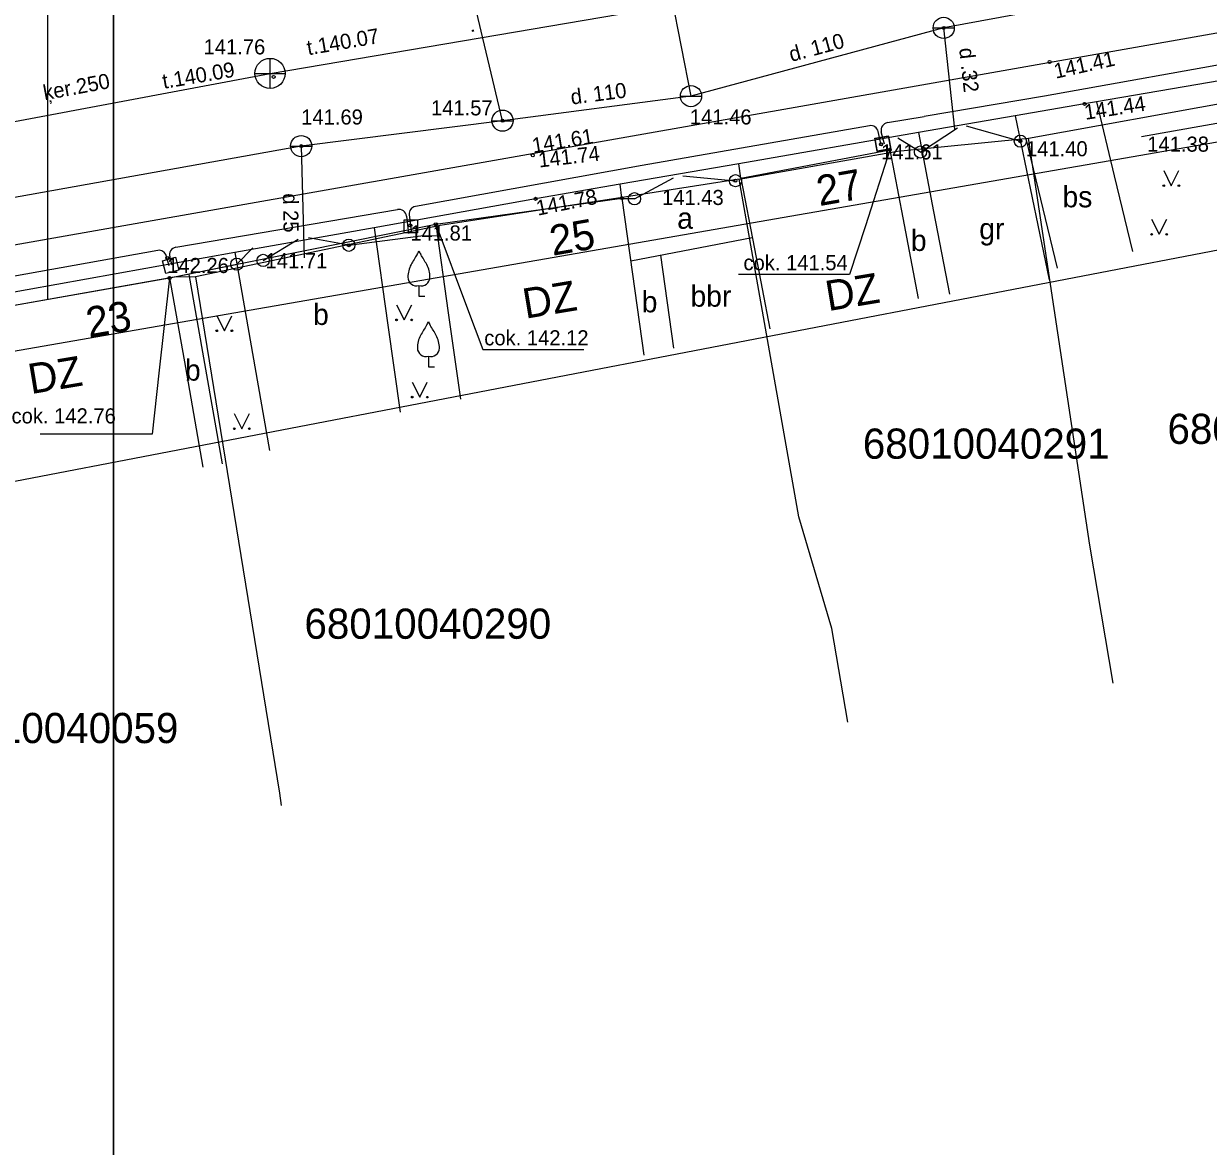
# Model space of a CAD drawing. Extents: x 728492 to 729038, y 272968 to 273171.
# Drawn here: x 728762.32 to 728801.6, y 273056.38 to 273093.59 of the extents above; entities that cross this region are included whole.
import ezdxf

# ---------------------------------------------------------------- set-up
doc = ezdxf.new("R2010")
doc.units = 0
for name, color, linetype in [('APGR_SARK_####_####_#', 7, 'Continuous'), ('BUVE_BDET_####_####_#', 7, 'Continuous'), ('BUVE_BDET_####_TKST_#', 7, 'Continuous'), ('BUVE_EKAS_####_####_#', 7, 'Continuous'), ('BUVE_EKAS_ADRS_TKST_#', 7, 'Continuous'), ('BUVE_EKAS_RAKS_TKST_#', 7, 'Continuous'), ('CELI_CAPM_####_####_#', 7, 'Continuous'), ('CELI_CMAL_####_####_#', 7, 'Continuous'), ('CELI_CSEG_####_TKST_#', 7, 'Continuous'), ('CELI_SEGL_####_####_#', 7, 'Continuous'), ('ELEK_ELEM_####_####_#', 7, 'Continuous'), ('ELEK_VADP_ZSPR_####_I', 7, 'Continuous'), ('NORB_ELEM_####_####_#', 7, 'Continuous'), ('NORB_ZOGS_BARJ_####_#', 7, 'Continuous'), ('NORB_ZOGS_ZSTP_####_#', 7, 'Continuous'), ('RAMI_PLAN_####_TKST_#', 7, 'Continuous'), ('RAMI_UZMR_####_####_#', 7, 'Continuous'), ('RELJ_AATZ_####_TKST_#', 7, 'Continuous'), ('RELJ_ELEM_####_####_#', 7, 'Continuous'), ('ROBZ_KADS_####_TKST_#', 7, 'Continuous'), ('ROBZ_UZMR_####_####_#', 7, 'Continuous'), ('SAKT_VADV_KLIN_####_#', 7, 'Continuous'), ('SKAN_ELEM_####_####_#', 7, 'Continuous'), ('SKAN_VADP_PAST_####_#', 7, 'Continuous'), ('SKAN_VADP_PAST_TKST_#', 7, 'Continuous'), ('TERT_ELEM_####_####_#', 7, 'Continuous'), ('TERT_KRND_####_####_#', 7, 'Continuous'), ('UDTK_ELEM_####_####_#', 7, 'Continuous'), ('UDTK_ELEM_####_TKST_#', 7, 'Continuous'), ('UDTK_VADP_UDEN_####_#', 7, 'Continuous'), ('UDTK_VADP_UDEN_TKST_#', 7, 'Continuous')]:
    doc.layers.add(name, color=color, linetype=linetype)

msp = doc.modelspace()

# ---------------------------------------------------------------- linework, layer by layer
at = {"layer": 'APGR_SARK_####_####_#'}
msp.add_lwpolyline([(728815.186, 273091.969), (728680.999, 273068.647)], dxfattribs=at)
at = {"layer": 'BUVE_BDET_####_####_#'}
for points in [[(728791.034, 273089.41), (728790.227, 273086.894)], [(728775.987, 273086.941), (728777.039, 273084.142)], [(728790.227, 273086.894), (728789.706, 273085.273), (728786.017, 273085.273)], [(728767.162, 273085.162), (728766.806, 273082.005)], [(728777.039, 273084.142), (728777.547, 273082.791), (728780.895, 273082.791)], [(728766.806, 273082.005), (728766.579, 273079.986), (728762.867, 273079.986)]]:
    msp.add_lwpolyline(points, dxfattribs=at)
at = {"layer": 'BUVE_EKAS_####_####_#'}
for p, q in [((728786.1, 273088.464), (728791.034, 273089.41)), ((728791.034, 273089.41), (728791.467, 273087.153)), ((728786.1, 273088.464), (728786.548, 273086.127)), ((728775.987, 273086.941), (728782.155, 273087.808)), ((728782.155, 273087.808), (728782.51, 273085.284)), ((728791.467, 273087.153), (728791.979, 273084.481)), ((728775.987, 273086.941), (728776.399, 273084.009)), ((728786.548, 273086.127), (728787.056, 273083.479)), ((728782.51, 273085.284), (728782.887, 273082.6)), ((728759.085, 273083.745), (728767.162, 273085.162)), ((728767.162, 273085.162), (728767.684, 273082.189)), ((728776.399, 273084.009), (728776.802, 273081.14)), ((728767.684, 273082.189), (728768.263, 273078.887))]:
    msp.add_line(p, q, dxfattribs=at)
at = {"layer": 'CELI_CAPM_####_####_#'}
msp.add_lwpolyline([(728676.374, 273071.049), (728680.397, 273071.606), (728696.384, 273074.602), (728721.076, 273079.042), (728739.743, 273082.405), (728759.114, 273085.751), (728811.654, 273095.023), (728814.654, 273095.178), (728815.22, 273095.032), (728815.785, 273094.657), (728816.384, 273093.154), (728816.384, 273093.154), (728817.477, 273084.163), (728819.159, 273072.476)], dxfattribs=at)
at = {"layer": 'CELI_CMAL_####_####_#'}
for p, q in [((728797.888, 273090.999), (728797.496, 273090.932)), ((728797.888, 273090.999), (728798.48, 273088.547)), ((728791.989, 273089.98), (728786.028, 273088.949)), ((728791.989, 273089.98), (728792.489, 273087.367)), ((728798.48, 273088.547), (728799.086, 273086.038)), ((728782.1, 273088.269), (728779.294, 273087.784)), ((728779.294, 273087.784), (728773.946, 273086.828)), ((728792.489, 273087.367), (728793.015, 273084.623)), ((728773.946, 273086.828), (728774.401, 273083.592)), ((728782.447, 273085.727), (728786.477, 273086.5)), ((728769.324, 273086.003), (728759.807, 273084.302)), ((728769.324, 273086.003), (728769.911, 273082.655)), ((728783.431, 273085.916), (728783.865, 273082.83)), ((728767.802, 273085.274), (728768.32, 273082.322)), ((728774.401, 273083.592), (728774.805, 273080.716)), ((728769.911, 273082.655), (728770.475, 273079.444)), ((728768.32, 273082.322), (728768.903, 273078.999))]:
    msp.add_line(p, q, dxfattribs=at)
for points in [[(728811.965, 273093.405), (728797.888, 273090.999)], [(728786.1, 273088.464), (728786.028, 273088.949)], [(728782.155, 273087.808), (728782.1, 273088.269)]]:
    msp.add_lwpolyline(points, dxfattribs=at)
at = {"layer": 'CELI_SEGL_####_####_#'}
for p, q in [((728797.496, 273090.932), (728795.19, 273090.533)), ((728795.19, 273090.533), (728791.989, 273089.98)), ((728786.028, 273088.949), (728782.1, 273088.269)), ((728773.946, 273086.828), (728769.324, 273086.003))]:
    msp.add_line(p, q, dxfattribs=at)
msp.add_lwpolyline([(728795.19, 273090.533), (728796.324, 273085.099)], dxfattribs=at)
at = {"layer": 'ELEK_ELEM_####_####_#'}
for points in [[(728791.057, 273089.44), (728790.617, 273089.364), (728790.541, 273089.797), (728790.982, 273089.874)], [(728791.072, 273089.428), (728790.632, 273089.346), (728790.552, 273089.779), (728790.992, 273089.86)], [(728775.381, 273086.653), (728774.934, 273086.653), (728774.934, 273087.093), (728775.381, 273087.093)], [(728767.472, 273085.421), (728767.039, 273085.308), (728766.928, 273085.733), (728767.361, 273085.846)]]:
    msp.add_lwpolyline(points, close=True, dxfattribs=at)
at = {"layer": 'ELEK_VADP_ZSPR_####_I'}
for p, q in [((728790.748, 273089.558), (728790.65, 273090.015)), ((728790.863, 273089.593), (728790.754, 273090.009)), ((728767.365, 273086.179), (728774.72, 273087.43)), ((728775.011, 273087.212), (728775.076, 273086.635)), ((728775.106, 273087.259), (728775.176, 273086.647)), ((728767.152, 273085.563), (728767.051, 273085.901)), ((728767.248, 273085.591), (728767.167, 273085.861))]:
    msp.add_line(p, q, dxfattribs=at)
for points in [[(728803.207, 273092.451), (728796.161, 273091.191), (728792.181, 273090.517)], [(728790.956, 273090.309), (728792.181, 273090.517)], [(728790.363, 273090.207), (728782.828, 273088.892), (728775.31, 273087.534)], [(728766.767, 273086.075), (728757.695, 273084.449), (728747.952, 273082.718)]]:
    msp.add_lwpolyline(points, dxfattribs=at)
for centre, start, end in [((728790.998, 273090.063), 99.6156, 192.4649), ((728790.406, 273089.961), 12.4649, 99.9014), ((728775.354, 273087.288), 100.2421, 186.5044), ((728774.762, 273087.184), 6.5044, 99.6552), ((728766.811, 273085.829), 16.7185, 100.1601), ((728767.406, 273085.932), 99.6552, 196.7185)]:
    msp.add_arc(centre, 0.25, start, end, dxfattribs=at)
at = {"layer": 'NORB_ELEM_####_####_#'}
for centre in [(728795.365, 273089.694), (728792.056, 273089.336), (728785.92, 273088.385), (728782.57, 273087.788), (728773.103, 273086.246), (728769.391, 273085.621), (728770.259, 273085.744)]:
    msp.add_circle(centre, 0.202, dxfattribs=at)
at = {"layer": 'NORB_ZOGS_BARJ_####_#'}
for points in [[(728792.056, 273089.336), (728793.281, 273090.133)], [(728793.572, 273090.205), (728795.365, 273089.694)], [(728792.056, 273089.336), (728791.304, 273089.793)], [(728782.57, 273087.788), (728783.87, 273088.478)], [(728784.176, 273088.542), (728785.92, 273088.385)], [(728782.57, 273087.788), (728781.966, 273087.788)], [(728770.259, 273085.744), (728771.423, 273086.448)], [(728773.103, 273086.246), (728771.764, 273086.487)], [(728769.391, 273085.621), (728769.922, 273086.157)]]:
    msp.add_lwpolyline(points, dxfattribs=at)
at = {"layer": 'NORB_ZOGS_ZSTP_####_#'}
for points in [[(728795.559, 273089.741), (728796.589, 273085.483)], [(728773.103, 273086.246), (728775.488, 273086.561), (728776.039, 273086.573)], [(728767.162, 273085.162), (728769.391, 273085.621)]]:
    msp.add_lwpolyline(points, dxfattribs=at)
at = {"layer": 'RAMI_PLAN_####_TKST_#'}
for points in [[(728765.305, 273170.927), (728765.305, 272986.902), (729038.383, 272986.902), (729038.383, 273170.927)], [(728492.227, 273152.288), (728492.227, 272968.263), (728765.305, 272968.263), (728765.305, 273152.288)]]:
    msp.add_lwpolyline(points, close=True, dxfattribs=at)
at = {"layer": 'RAMI_UZMR_####_####_#'}
msp.add_lwpolyline([(728688.721, 273058.407), (728702.149, 273066.922), (728733.452, 273072.937), (728813.127, 273088.247), (728815.181, 273072.879), (728831.342, 273076.994), (728831.817, 273091.35), (728930.137, 273106.573), (728962.389, 273111.567), (728966.363, 273103.835), (728988.796, 273109.153), (728985.811, 273141.417), (728955.146, 273144.603), (728957.616, 273137.975), (728904.333, 273130.641), (728847.677, 273120.095), (728823.483, 273119.793), (728790.036, 273112.558), (728726.814, 273102.175), (728686.914, 273096.216)], dxfattribs=at)
at = {"layer": 'RELJ_ELEM_####_####_#'}
for centre in [(728792.824, 273093.45), (728796.335, 273092.318), (728770.61, 273091.825), (728797.496, 273090.932), (728778.198, 273090.374), (728771.523, 273089.532), (728790.746, 273089.591), (728795.365, 273089.694), (728779.201, 273089.227), (728791.034, 273089.41), (728785.92, 273088.385), (728779.294, 273087.784), (728782.155, 273087.808), (728775.141, 273086.902), (728775.987, 273086.941), (728773.103, 273086.246), (728767.082, 273085.825), (728767.162, 273085.162)]:
    msp.add_circle(centre, 0.05, dxfattribs=at)
at = {"layer": 'ROBZ_UZMR_####_####_#'}
for p, q in [((728795.632, 273089.795), (728812.375, 273092.814)), ((728791.29, 273089.36), (728795.632, 273089.795)), ((728797.668, 273076.307), (728795.632, 273089.795)), ((728786.046, 273088.437), (728791.29, 273089.36)), ((728786.046, 273088.437), (728782.312, 273087.85)), ((728788.022, 273077.242), (728786.046, 273088.437)), ((728782.312, 273087.85), (728776.135, 273086.901)), ((728776.135, 273086.901), (728768.022, 273085.199)), ((728767.308, 273085.186), (728759.065, 273083.724)), ((728768.022, 273085.199), (728767.308, 273085.186)), ((728768.022, 273085.199), (728770.799, 273068.087)), ((728789.116, 273073.544), (728788.022, 273077.242)), ((728798.447, 273071.731), (728797.668, 273076.307)), ((728789.646, 273070.437), (728789.116, 273073.544)), ((728770.799, 273068.087), (728770.865, 273067.675))]:
    msp.add_line(p, q, dxfattribs=at)
at = {"layer": 'SAKT_VADV_KLIN_####_#'}
for points in [[(728763.123, 273084.454), (728763.123, 273103.948)], [(728767.162, 273085.162), (728775.987, 273086.941)]]:
    msp.add_lwpolyline(points, dxfattribs=at)
at = {"layer": 'SKAN_ELEM_####_####_#'}
for p, q in [((728770.492, 273091.441), (728770.492, 273092.441)), ((728769.992, 273091.941), (728770.992, 273091.941))]:
    msp.add_line(p, q, dxfattribs=at)
msp.add_circle((728770.492, 273091.941), 0.5, dxfattribs=at)
at = {"layer": 'SKAN_VADP_PAST_####_#'}
msp.add_lwpolyline([(728754.421, 273088.922), (728770.492, 273091.941), (728805.243, 273097.85), (728806.524, 273091.029)], dxfattribs=at)
at = {"layer": 'TERT_ELEM_####_####_#'}
for p, q in [((728800.12, 273088.719), (728800.37, 273088.219)), ((728800.37, 273088.219), (728800.62, 273088.719)), ((728799.717, 273087.108), (728799.967, 273086.608)), ((728799.967, 273086.608), (728800.217, 273087.108)), ((728775.426, 273084.911), (728775.426, 273084.559)), ((728775.426, 273084.559), (728775.626, 273084.559)), ((728774.686, 273084.273), (728774.936, 273083.773)), ((728774.936, 273083.773), (728775.186, 273084.273)), ((728768.726, 273083.911), (728768.976, 273083.411)), ((728768.976, 273083.411), (728769.226, 273083.911)), ((728775.741, 273082.565), (728775.741, 273082.213)), ((728775.741, 273082.213), (728775.941, 273082.213)), ((728775.204, 273081.711), (728775.454, 273081.211)), ((728775.454, 273081.211), (728775.704, 273081.711)), ((728769.305, 273080.664), (728769.555, 273080.164)), ((728769.555, 273080.164), (728769.805, 273080.664))]:
    msp.add_line(p, q, dxfattribs=at)
for centre, radius in [((728800.12, 273088.219), 0.028), ((728800.62, 273088.219), 0.0263), ((728799.717, 273086.607), 0.028), ((728800.217, 273086.607), 0.0263), ((728774.686, 273083.772), 0.028), ((728775.186, 273083.772), 0.0263), ((728768.726, 273083.411), 0.028), ((728769.226, 273083.411), 0.0263), ((728775.203, 273081.211), 0.028), ((728775.703, 273081.211), 0.0263), ((728769.305, 273080.164), 0.028), ((728769.805, 273080.164), 0.0263)]:
    msp.add_circle(centre, radius, dxfattribs=at)
for centre, radius, start, end in [((728775.009, 273086.197), 0.439, 324.3837, 341.712), ((728775.843, 273086.197), 0.439, 198.288, 215.6163), ((728775.95, 273085.184), 0.89, 151.757, 179.9138), ((728788.051, 273078.163), 14.88, 148.4844, 149.9901), ((728762.801, 273078.163), 14.88, 30.0099, 31.5156), ((728774.902, 273085.184), 0.89, 0.0862, 28.243), ((728775.35, 273085.19), 0.29, 181.0782, 285.2823), ((728775.502, 273085.19), 0.29, 254.7177, 358.9218), ((728775.324, 273083.851), 0.439, 324.3837, 341.712), ((728776.158, 273083.851), 0.439, 198.288, 215.6163), ((728776.265, 273082.838), 0.89, 151.757, 179.9138), ((728788.366, 273075.817), 14.88, 148.4844, 149.9901), ((728763.116, 273075.817), 14.88, 30.0099, 31.5156), ((728775.217, 273082.838), 0.89, 0.0862, 28.243), ((728775.665, 273082.844), 0.29, 181.0782, 285.2823), ((728775.817, 273082.844), 0.29, 254.7177, 358.9218)]:
    msp.add_arc(centre, radius, start, end, dxfattribs=at)
at = {"layer": 'TERT_KRND_####_####_#'}
msp.add_lwpolyline([(728799.386, 273089.847), (728804.683, 273090.786)], dxfattribs=at)
at = {"layer": 'UDTK_ELEM_####_####_#'}
for p, q in [((728792.473, 273093.45), (728793.175, 273093.45)), ((728792.823, 273093.45), (728792.823, 273093.451)), ((728784.095, 273091.188), (728784.797, 273091.188)), ((728784.445, 273091.188), (728784.445, 273091.189)), ((728777.847, 273090.374), (728778.549, 273090.374)), ((728778.197, 273090.374), (728778.197, 273090.375)), ((728771.172, 273089.532), (728771.874, 273089.532)), ((728771.522, 273089.532), (728771.522, 273089.533))]:
    msp.add_line(p, q, dxfattribs=at)
for centre in [(728792.824, 273093.45), (728784.446, 273091.188), (728778.198, 273090.374), (728771.523, 273089.532)]:
    msp.add_circle(centre, 0.351, dxfattribs=at)
at = {"layer": 'UDTK_VADP_UDEN_####_#'}
for p, q in [((728782.354, 273101.802), (728784.446, 273091.188)), ((728778.198, 273090.374), (728775.631, 273101.102)), ((728810.333, 273096.686), (728792.824, 273093.45)), ((728792.824, 273093.45), (728784.446, 273091.188)), ((728793.197, 273090.093), (728792.824, 273093.45)), ((728784.446, 273091.188), (728778.198, 273090.374)), ((728778.198, 273090.374), (728771.523, 273089.532)), ((728771.523, 273089.532), (728771.619, 273085.826))]:
    msp.add_line(p, q, dxfattribs=at)
msp.add_lwpolyline([(728771.523, 273089.532), (728756.89, 273086.908), (728750.695, 273085.496)], dxfattribs=at)

# ---------------------------------------------------------------- texts
at = {"layer": 'BUVE_BDET_####_TKST_#'}
for s, p in [('cok. 141.54', (728786.185, 273085.419)), ('cok. 142.12', (728777.593, 273082.928)), ('cok. 142.76', (728761.921, 273080.341))]:
    msp.add_text(s, height=0.49999, dxfattribs=at).set_placement(p)
at = {"layer": 'BUVE_EKAS_ADRS_TKST_#'}
for s, p in [('27', (728788.703, 273087.541)), ('25', (728779.857, 273085.894)), ('23', (728764.488, 273083.182))]:
    msp.add_text(s, height=1, rotation=9.951, dxfattribs=at).set_placement(p)
at = {"layer": 'BUVE_EKAS_RAKS_TKST_#'}
for p in [(728788.994, 273084.061), (728778.958, 273083.807), (728762.564, 273081.31)]:
    msp.add_text('DZ', height=1, rotation=9.431, dxfattribs=at).set_placement(p)
at = {"layer": 'CELI_CSEG_####_TKST_#'}
for s, p in [('bs', (728796.763, 273087.503)), ('a', (728783.989, 273086.793)), ('b', (728791.736, 273086.056)), ('gr', (728794.002, 273086.443)), ('bbr', (728784.431, 273084.209)), ('b', (728782.814, 273084.022)), ('b', (728771.919, 273083.604)), ('b', (728767.67, 273081.758))]:
    msp.add_text(s, height=0.7, dxfattribs=at).set_placement(p)
at = {"layer": 'RELJ_AATZ_####_TKST_#'}
for s, rotation, p in [('141.41', 12.5388, (728796.539, 273091.764)), ('141.44', 8.6378, (728797.523, 273090.402)), ('141.61', 9.2374, (728779.218, 273089.299)), ('141.74', 6.5394, (728779.413, 273088.821)), ('141.78', 11.3956, (728779.367, 273087.224))]:
    msp.add_text(s, height=0.5, rotation=rotation, dxfattribs=at).set_placement(p)
for s, p in [('141.61', (728790.746, 273089.091)), (' 141.40', (728795.365, 273089.194)), (' 141.38', (728799.386, 273089.347)), (' 141.43', (728783.3, 273087.58)), ('141.81', (728775.141, 273086.402)), (' 141.71', (728770.157, 273085.485)), ('142.26', (728767.082, 273085.325))]:
    msp.add_text(s, height=0.5, dxfattribs=at).set_placement(p)
at = {"layer": 'ROBZ_KADS_####_TKST_#'}
for s, p in [('68010040074', (728800.243, 273079.661)), ('68010040291', (728790.143, 273079.17)), ('68010040290', (728771.631, 273073.203)), ('68010040059', (728759.272, 273069.745))]:
    msp.add_text(s, height=1, dxfattribs=at).set_placement(p)
at = {"layer": 'SKAN_ELEM_####_####_#'}
msp.add_text('141.76', height=0.5, dxfattribs=at).set_placement((728768.288, 273092.572))
at = {"layer": 'SKAN_VADP_PAST_TKST_#'}
for s, rotation, p in [('t.140.07', 9.73, (728771.756, 273092.541)), ('t.140.09', 9.73, (728766.967, 273091.428)), ('ķer.250', 10.642, (728763.02, 273091.047))]:
    msp.add_text(s, height=0.5, rotation=rotation, dxfattribs=at).set_placement(p)
at = {"layer": 'UDTK_ELEM_####_TKST_#'}
for s, p in [('141.69', (728771.523, 273090.247)), ('141.57', (728775.826, 273090.55)), ('141.46', (728784.409, 273090.249))]:
    msp.add_text(s, height=0.5, dxfattribs=at).set_placement(p)
at = {"layer": 'UDTK_VADP_UDEN_TKST_#'}
for s, rotation, p in [('.', 283.456, (728777.156, 273093.439)), ('d. 110', 15.1092, (728787.774, 273092.32)), ('d .32', 276.3402, (728793.334, 273092.766)), ('d. 110', 7.4228, (728780.489, 273090.906)), ('d 25', 271.2882, (728770.913, 273087.964))]:
    msp.add_text(s, height=0.5, rotation=rotation, dxfattribs=at).set_placement(p)

doc.saveas('drawing.dxf')
